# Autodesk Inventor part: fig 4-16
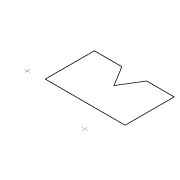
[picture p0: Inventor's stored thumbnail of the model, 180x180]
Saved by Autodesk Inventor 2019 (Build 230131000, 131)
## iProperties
Created: 2005-02
Part Number: fig 4-16
Document SubType Name: Modeling
Designer: CADCIM
Manufacturer: Standard
Standards Organization: Custom
Density: 1 g/cm^3
Material: Generic
Appearance: Default
Author: CADCIM
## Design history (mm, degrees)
sketch "Sketch1"
  geometry: L1 (-25.19, 27.524)-(-25.19, 5.557); L2 (-25.19, 5.557)-(10.567, 5.557); L3 (10.567, 5.557)-(10.567, 27.524); L4 (10.567, 27.524)-(-1.76, 27.524); L5 (-1.76, 27.524)-(-7.312, 18.449); L6 (-7.312, 18.449)-(-12.863, 27.524); L7 (-12.863, 27.524)-(-25.19, 27.524); 2 further points
  constraints: 14 end point, 3 equal length, 3 parallel, 1 perpendicular, 1 vertical, 1 other
